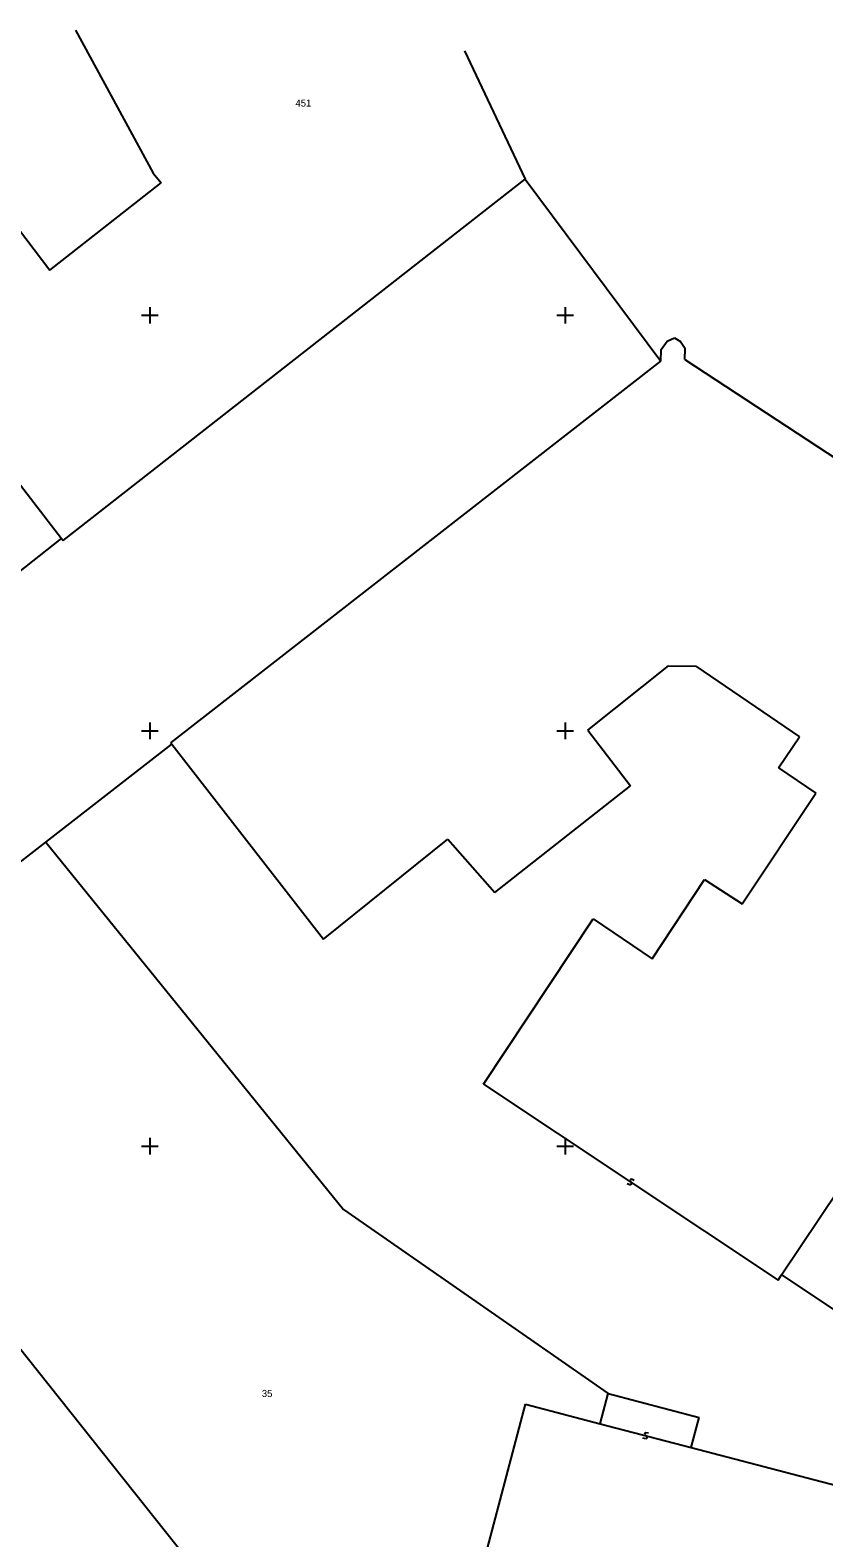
# Model space of a CAD drawing. Extents: x -492811 to -492366, y -1127107 to -1126748.
# Drawn here: x -492585.8 to -492547.5, y -1126838.9 to -1126766.3 of the extents above; entities that cross this region are included whole.
import ezdxf

# ---------------------------------------------------------------- set-up
doc = ezdxf.new("R2010")
doc.units = 0
doc.layers.add('katastrální mapa', color=7, linetype='Continuous')
doc.layers.add('síť', color=7, linetype='Continuous')

msp = doc.modelspace()

# ---------------------------------------------------------------- linework, layer by layer
at = {"layer": 'katastrální mapa'}
for p, q in [((-492583.57, -1126766.27), (-492579.83, -1126773.16)), ((-492564.84, -1126767.26), (-492561.92, -1126773.45)), ((-492584.8, -1126777.82), (-492579.45, -1126773.62)), ((-492584.17, -1126790.84), (-492561.92, -1126773.45)), ((-492579.83, -1126773.16), (-492579.45, -1126773.62)), ((-492561.92, -1126773.45), (-492555.4, -1126782.2)), ((-492586.72, -1126775.3), (-492584.8, -1126777.82)), ((-492592.66, -1126779.84), (-492584.24, -1126790.75)), ((-492555.38, -1126781.65), (-492555.09, -1126781.25)), ((-492555.09, -1126781.25), (-492554.73, -1126781.09)), ((-492554.73, -1126781.09), (-492554.45, -1126781.26)), ((-492554.45, -1126781.26), (-492554.22, -1126781.6)), ((-492554.24, -1126782.12), (-492554.22, -1126781.6)), ((-492578.99, -1126800.58), (-492555.4, -1126782.2)), ((-492555.4, -1126782.2), (-492555.38, -1126781.65)), ((-492554.24, -1126782.12), (-492542.08, -1126790.12)), ((-492587.55, -1126793.36), (-492584.24, -1126790.75)), ((-492584.24, -1126790.75), (-492584.17, -1126790.84)), ((-492558.9, -1126799.97), (-492555.03, -1126796.88)), ((-492555.03, -1126796.88), (-492553.7, -1126796.89)), ((-492553.7, -1126796.89), (-492548.71, -1126800.3)), ((-492558.9, -1126799.97), (-492556.85, -1126802.66)), ((-492549.73, -1126801.78), (-492548.71, -1126800.3)), ((-492585, -1126805.36), (-492578.94, -1126800.65)), ((-492578.99, -1126800.58), (-492578.94, -1126800.65)), ((-492578.94, -1126800.65), (-492571.64, -1126810.04)), ((-492549.73, -1126801.78), (-492547.93, -1126803.01)), ((-492563.39, -1126807.79), (-492556.85, -1126802.66)), ((-492551.48, -1126808.34), (-492547.93, -1126803.01)), ((-492597.76, -1126815.28), (-492585, -1126805.36)), ((-492585, -1126805.36), (-492570.67, -1126823.06)), ((-492571.64, -1126810.04), (-492565.64, -1126805.22)), ((-492565.64, -1126805.22), (-492563.39, -1126807.79)), ((-492555.81, -1126810.98), (-492553.29, -1126807.16)), ((-492553.29, -1126807.16), (-492551.48, -1126808.34)), ((-492563.93, -1126817.02), (-492558.65, -1126809.06)), ((-492558.65, -1126809.06), (-492555.81, -1126810.98)), ((-492597.76, -1126815.28), (-492568.28, -1126852.33)), ((-492563.93, -1126817.02), (-492549.75, -1126826.45)), ((-492549.58, -1126826.2), (-492544.46, -1126818.54)), ((-492556.88, -1126821.87), (-492557.01, -1126821.81)), ((-492556.83, -1126821.86), (-492556.88, -1126821.87)), ((-492556.85, -1126821.61), (-492556.87, -1126821.64)), ((-492556.87, -1126821.64), (-492556.86, -1126821.7)), ((-492556.86, -1126821.7), (-492556.82, -1126821.77)), ((-492556.8, -1126821.6), (-492556.85, -1126821.61)), ((-492556.81, -1126821.83), (-492556.83, -1126821.86)), ((-492556.82, -1126821.77), (-492556.81, -1126821.83)), ((-492556.67, -1126821.66), (-492556.8, -1126821.6)), ((-492570.67, -1126823.06), (-492557.93, -1126831.92)), ((-492549.75, -1126826.45), (-492549.58, -1126826.2)), ((-492549.58, -1126826.2), (-492545.47, -1126828.95)), ((-492566.27, -1126848.94), (-492561.91, -1126832.42)), ((-492561.91, -1126832.42), (-492558.31, -1126833.37)), ((-492558.31, -1126833.37), (-492557.93, -1126831.92)), ((-492557.93, -1126831.92), (-492553.55, -1126833.07)), ((-492553.93, -1126834.52), (-492553.55, -1126833.07)), ((-492558.31, -1126833.37), (-492553.93, -1126834.52)), ((-492556.17, -1126833.83), (-492556.18, -1126833.87)), ((-492556.18, -1126833.87), (-492556.15, -1126833.92)), ((-492556.12, -1126833.8), (-492556.17, -1126833.83)), ((-492555.98, -1126833.82), (-492556.12, -1126833.8)), ((-492556.12, -1126834.09), (-492556.26, -1126834.07)), ((-492556.15, -1126833.92), (-492556.09, -1126833.97)), ((-492556.07, -1126834.06), (-492556.12, -1126834.09)), ((-492556.09, -1126833.97), (-492556.06, -1126834.02)), ((-492556.06, -1126834.02), (-492556.07, -1126834.06)), ((-492553.93, -1126834.52), (-492542.13, -1126837.61))]:
    msp.add_line(p, q, dxfattribs=at)
at = {"layer": 'síť'}
for p, q in [((-492580.4, -1126780), (-492579.6, -1126780)), ((-492580, -1126779.6), (-492580, -1126780.4)), ((-492560.4, -1126780), (-492559.6, -1126780)), ((-492560, -1126779.6), (-492560, -1126780.4)), ((-492580, -1126799.6), (-492580, -1126800.4)), ((-492560, -1126799.6), (-492560, -1126800.4)), ((-492580.4, -1126800), (-492579.6, -1126800)), ((-492560.4, -1126800), (-492559.6, -1126800)), ((-492580.4, -1126820), (-492579.6, -1126820)), ((-492580, -1126819.6), (-492580, -1126820.4)), ((-492560.4, -1126820), (-492559.6, -1126820)), ((-492560, -1126819.6), (-492560, -1126820.4))]:
    msp.add_line(p, q, dxfattribs=at)

# ---------------------------------------------------------------- texts
at = {"layer": 'katastrální mapa'}
for s, p in [('451', (-492572.98, -1126769.95)), ('35', (-492574.6, -1126832.08))]:
    msp.add_text(s, height=0.34, dxfattribs=at).set_placement(p)

doc.saveas('drawing.dxf')
